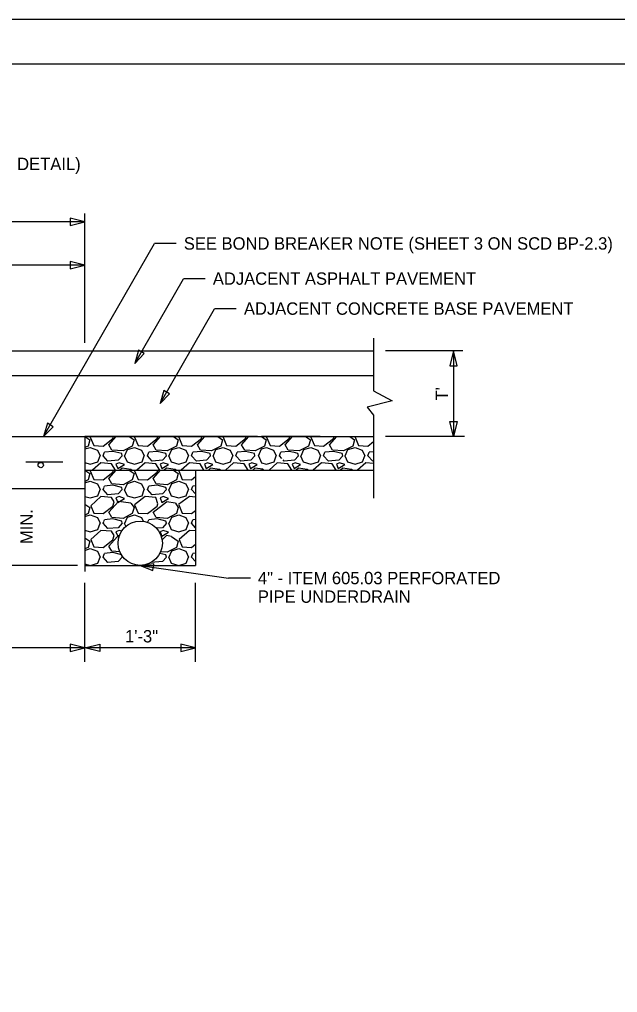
# Model space of a CAD drawing. Extents: x -529 to 1, y -1131 to -115.
# Drawn here: x -332.7 to -265.2, y -1020.8 to -910.8 of the extents above; entities that cross this region are included whole.
import ezdxf

# ---------------------------------------------------------------- set-up
doc = ezdxf.new("R2010")
doc.units = 0
for name, color, linetype in [('SH_Border', 7, 'Continuous'), ('SH_Cut_Line', 7, 'Continuous'), ('SH_Data', 7, 'Continuous'), ('SH_Text', 7, 'Continuous'), ('TX_X_5', 7, 'Continuous')]:
    doc.layers.add(name, color=color, linetype=linetype)

msp = doc.modelspace()

# ---------------------------------------------------------------- linework, layer by layer
at = {"layer": 'SH_Border'}
msp.add_lwpolyline([(-509.28, -915.76), (-194.28, -915.76), (-194.28, -1125.76), (-509.28, -1125.76)], close=True, dxfattribs=at)
at = {"layer": 'SH_Cut_Line'}
msp.add_lwpolyline([(-529.28, -1130.76), (-189.28, -1130.76), (-189.28, -910.76), (-529.28, -910.76)], close=True, dxfattribs=at)
at = {"layer": 'SH_Data'}
for p, q in [((-414.82, -948.22), (-292.72, -948.22)), ((-345.34, -951), (-292.72, -951)), ((-365.34, -957.9), (-292.72, -957.9)), ((-325.34, -957.9), (-325.34, -972.47)), ((-325.34, -957.9), (-305.86, -957.9)), ((-318.7, -957.9), (-325.34, -957.9)), ((-325.34, -957.9), (-325.34, -961.11)), ((-325.34, -957.9), (-324.79, -958.28)), ((-324.74, -957.9), (-324.74, -957.98)), ((-324.74, -957.98), (-324.34, -958.93)), ((-322.64, -958.83), (-321.81, -957.9)), ((-322.19, -958.13), (-322.12, -957.9)), ((-320.34, -957.9), (-319.79, -958.28)), ((-319.74, -957.9), (-319.74, -957.98)), ((-319.74, -957.98), (-319.34, -958.93)), ((-305.86, -957.9), (-318.7, -957.9)), ((-317.64, -958.83), (-316.81, -957.9)), ((-317.19, -958.13), (-317.12, -957.9)), ((-315.34, -957.9), (-314.79, -958.28)), ((-314.74, -957.9), (-314.74, -957.98)), ((-314.74, -957.98), (-314.34, -958.93)), ((-312.64, -958.83), (-311.81, -957.9)), ((-312.19, -958.13), (-312.12, -957.9)), ((-310.34, -957.9), (-309.79, -958.28)), ((-309.74, -957.9), (-309.74, -957.98)), ((-309.74, -957.98), (-309.34, -958.93)), ((-307.64, -958.83), (-306.81, -957.9)), ((-307.19, -958.13), (-307.12, -957.9)), ((-298.77, -957.9), (-305.41, -957.9)), ((-305.41, -957.9), (-304.87, -958.28)), ((-304.81, -957.9), (-304.82, -957.98)), ((-304.82, -957.98), (-304.42, -958.93)), ((-302.72, -958.83), (-301.88, -957.9)), ((-302.27, -958.13), (-302.19, -957.9)), ((-300.41, -957.9), (-299.87, -958.28)), ((-299.81, -957.9), (-299.82, -957.98)), ((-299.82, -957.98), (-299.42, -958.93)), ((-297.72, -958.83), (-296.88, -957.9)), ((-297.27, -958.13), (-297.19, -957.9)), ((-295.41, -957.9), (-294.87, -958.28)), ((-294.81, -957.9), (-294.82, -957.98)), ((-294.82, -957.98), (-294.42, -958.93)), ((-324.99, -958.98), (-325.34, -959.16)), ((-325.34, -959.31), (-324.74, -959.13)), ((-324.79, -958.28), (-324.99, -958.98)), ((-324.74, -959.13), (-323.94, -959.43)), ((-324.34, -958.93), (-323.29, -958.98)), ((-323.29, -958.98), (-322.19, -958.13)), ((-322.29, -959.43), (-322.64, -958.83)), ((-319.99, -958.98), (-321.04, -959.53)), ((-320.54, -959.38), (-319.74, -959.13)), ((-319.79, -958.28), (-319.99, -958.98)), ((-319.74, -959.13), (-318.94, -959.43)), ((-319.34, -958.93), (-318.29, -958.98)), ((-318.29, -958.98), (-317.19, -958.13)), ((-317.29, -959.43), (-317.64, -958.83)), ((-314.99, -958.98), (-316.04, -959.53)), ((-315.54, -959.38), (-314.74, -959.13)), ((-314.79, -958.28), (-314.99, -958.98)), ((-314.74, -959.13), (-313.94, -959.43)), ((-314.34, -958.93), (-313.29, -958.98)), ((-313.29, -958.98), (-312.19, -958.13)), ((-312.29, -959.43), (-312.64, -958.83)), ((-309.99, -958.98), (-311.04, -959.53)), ((-310.54, -959.38), (-309.74, -959.13)), ((-309.79, -958.28), (-309.99, -958.98)), ((-309.74, -959.13), (-308.94, -959.43)), ((-309.34, -958.93), (-308.29, -958.98)), ((-308.29, -958.98), (-307.19, -958.13)), ((-307.29, -959.43), (-307.64, -958.83)), ((-305.07, -958.99), (-306.1, -959.52)), ((-305.4, -959.31), (-304.82, -959.13)), ((-304.87, -958.28), (-305.07, -958.99)), ((-304.82, -959.13), (-304.02, -959.43)), ((-304.42, -958.93), (-303.37, -958.98)), ((-303.37, -958.98), (-302.27, -958.13)), ((-302.37, -959.43), (-302.72, -958.83)), ((-300.07, -958.98), (-301.12, -959.53)), ((-300.62, -959.38), (-299.82, -959.13)), ((-299.87, -958.28), (-300.07, -958.98)), ((-299.82, -959.13), (-299.02, -959.43)), ((-299.42, -958.93), (-298.37, -958.98)), ((-298.37, -958.98), (-297.27, -958.13)), ((-297.37, -959.43), (-297.72, -958.83)), ((-295.07, -958.98), (-296.12, -959.53)), ((-295.62, -959.38), (-294.82, -959.13)), ((-294.87, -958.28), (-295.07, -958.98)), ((-294.82, -959.13), (-294.02, -959.43)), ((-294.42, -958.93), (-293.37, -958.98)), ((-293.37, -958.98), (-292.72, -958.48)), ((-323.94, -959.43), (-323.64, -960.08)), ((-323.89, -960.78), (-323.64, -960.08)), ((-323.29, -960.08), (-323.22, -959.87)), ((-322.74, -960.68), (-323.29, -960.08)), ((-323.21, -959.86), (-323.14, -959.68)), ((-322.19, -959.58), (-323.14, -959.68)), ((-321.04, -959.53), (-322.29, -959.43)), ((-321.19, -959.83), (-322.19, -959.58)), ((-321.14, -960.08), (-321.59, -960.58)), ((-321.14, -960.08), (-321.19, -959.83)), ((-320.87, -960.14), (-320.54, -959.38)), ((-320.87, -960.14), (-320.59, -960.78)), ((-318.94, -959.43), (-318.64, -960.08)), ((-318.89, -960.78), (-318.64, -960.08)), ((-318.29, -960.08), (-318.14, -959.68)), ((-317.74, -960.68), (-318.29, -960.08)), ((-317.19, -959.58), (-318.14, -959.68)), ((-316.04, -959.53), (-317.29, -959.43)), ((-316.19, -959.83), (-317.19, -959.58)), ((-316.14, -960.08), (-316.59, -960.58)), ((-316.14, -960.08), (-316.19, -959.83)), ((-315.87, -960.14), (-315.54, -959.38)), ((-315.87, -960.14), (-315.59, -960.78)), ((-313.94, -959.43), (-313.64, -960.08)), ((-313.89, -960.78), (-313.64, -960.08)), ((-313.29, -960.08), (-313.14, -959.68)), ((-312.74, -960.68), (-313.29, -960.08)), ((-312.19, -959.58), (-313.14, -959.68)), ((-311.04, -959.53), (-312.29, -959.43)), ((-311.19, -959.83), (-312.19, -959.58)), ((-311.14, -960.08), (-311.59, -960.58)), ((-311.14, -960.08), (-311.19, -959.83)), ((-310.87, -960.14), (-310.54, -959.38)), ((-310.87, -960.14), (-310.59, -960.78)), ((-308.94, -959.43), (-308.64, -960.08)), ((-308.89, -960.78), (-308.64, -960.08)), ((-308.29, -960.08), (-308.14, -959.68)), ((-307.74, -960.68), (-308.29, -960.08)), ((-307.19, -959.58), (-308.14, -959.68)), ((-306.1, -959.52), (-307.29, -959.43)), ((-306.19, -959.83), (-307.19, -959.58)), ((-306.14, -960.08), (-306.59, -960.58)), ((-306.14, -960.08), (-306.19, -959.83)), ((-305.73, -960.08), (-305.4, -959.31)), ((-305.73, -960.08), (-305.39, -960.86)), ((-304.02, -959.43), (-303.72, -960.08)), ((-303.97, -960.78), (-303.72, -960.08)), ((-303.37, -960.08), (-303.29, -959.87)), ((-303.08, -960.39), (-303.37, -960.08)), ((-303.28, -959.86), (-303.22, -959.68)), ((-302.27, -959.58), (-303.22, -959.68)), ((-301.12, -959.53), (-302.37, -959.43)), ((-301.9, -959.67), (-302.27, -959.58)), ((-301.27, -959.83), (-301.81, -959.69)), ((-301.22, -960.08), (-301.67, -960.58)), ((-301.22, -960.08), (-301.27, -959.83)), ((-300.97, -960.08), (-300.67, -960.78)), ((-300.92, -960.08), (-300.62, -959.38)), ((-299.02, -959.43), (-298.72, -960.08)), ((-298.97, -960.78), (-298.72, -960.08)), ((-298.37, -960.08), (-298.22, -959.68)), ((-297.82, -960.68), (-298.37, -960.08)), ((-297.27, -959.58), (-298.22, -959.68)), ((-296.12, -959.53), (-297.37, -959.43)), ((-296.27, -959.83), (-297.27, -959.58)), ((-296.22, -960.08), (-296.67, -960.58)), ((-296.22, -960.08), (-296.27, -959.83)), ((-295.97, -960.08), (-295.67, -960.78)), ((-295.92, -960.08), (-295.62, -959.38)), ((-294.02, -959.43), (-293.72, -960.08)), ((-293.97, -960.78), (-293.72, -960.08)), ((-293.37, -960.08), (-293.22, -959.68)), ((-292.82, -960.68), (-293.37, -960.08)), ((-292.72, -959.63), (-293.22, -959.68)), ((-332.04, -960.76), (-327.84, -960.76)), ((-325.34, -960.85), (-324.74, -961.03)), ((-325.34, -961.11), (-325.34, -961.72)), ((-324.74, -961.03), (-323.89, -960.78)), ((-323.54, -960.88), (-324.47, -961.72)), ((-322.34, -960.98), (-323.54, -960.88)), ((-321.59, -960.58), (-322.74, -960.68)), ((-321.89, -961.72), (-322.34, -960.98)), ((-321.49, -960.88), (-321.84, -961.03)), ((-321.84, -961.03), (-321.64, -961.53)), ((-321.64, -961.53), (-320.89, -961.08)), ((-320.89, -961.08), (-321.49, -960.88)), ((-320.59, -960.78), (-319.74, -961.03)), ((-319.74, -961.03), (-318.89, -960.78)), ((-318.54, -960.88), (-319.47, -961.72)), ((-317.34, -960.98), (-318.54, -960.88)), ((-316.59, -960.58), (-317.74, -960.68)), ((-316.89, -961.72), (-317.34, -960.98)), ((-316.49, -960.88), (-316.84, -961.03)), ((-316.84, -961.03), (-316.64, -961.53)), ((-316.64, -961.53), (-315.89, -961.08)), ((-315.89, -961.08), (-316.49, -960.88)), ((-315.59, -960.78), (-314.74, -961.03)), ((-314.74, -961.03), (-313.89, -960.78)), ((-313.54, -960.88), (-314.47, -961.72)), ((-312.34, -960.98), (-313.54, -960.88)), ((-311.59, -960.58), (-312.74, -960.68)), ((-311.89, -961.72), (-312.34, -960.98)), ((-311.49, -960.88), (-311.84, -961.03)), ((-311.84, -961.03), (-311.64, -961.53)), ((-311.64, -961.53), (-310.89, -961.08)), ((-310.89, -961.08), (-311.49, -960.88)), ((-310.59, -960.78), (-309.74, -961.03)), ((-309.74, -961.03), (-308.89, -960.78)), ((-308.54, -960.88), (-309.47, -961.72)), ((-307.34, -960.98), (-308.54, -960.88)), ((-306.59, -960.58), (-307.74, -960.68)), ((-306.89, -961.72), (-307.34, -960.98)), ((-306.49, -960.88), (-306.84, -961.03)), ((-306.84, -961.03), (-306.64, -961.53)), ((-306.64, -961.53), (-305.89, -961.08)), ((-305.89, -961.08), (-306.49, -960.88)), ((-305.39, -960.86), (-304.82, -961.03)), ((-304.82, -961.03), (-303.97, -960.78)), ((-303.62, -960.88), (-304.54, -961.72)), ((-302.42, -960.98), (-303.62, -960.88)), ((-302.82, -960.68), (-302.96, -960.52)), ((-301.67, -960.58), (-302.82, -960.68)), ((-301.96, -961.72), (-302.42, -960.98)), ((-301.57, -960.88), (-301.92, -961.03)), ((-301.92, -961.03), (-301.72, -961.53)), ((-301.72, -961.53), (-300.97, -961.08)), ((-300.97, -961.08), (-301.57, -960.88)), ((-300.67, -960.78), (-299.82, -961.03)), ((-299.82, -961.03), (-298.97, -960.78)), ((-298.62, -960.88), (-299.54, -961.72)), ((-297.42, -960.98), (-298.62, -960.88)), ((-296.67, -960.58), (-297.82, -960.68)), ((-296.96, -961.72), (-297.42, -960.98)), ((-296.57, -960.88), (-296.92, -961.03)), ((-296.92, -961.03), (-296.72, -961.53)), ((-296.72, -961.53), (-295.97, -961.08)), ((-295.97, -961.08), (-296.57, -960.88)), ((-295.67, -960.78), (-294.82, -961.03)), ((-294.82, -961.03), (-293.97, -960.78)), ((-293.62, -960.88), (-294.54, -961.72)), ((-292.72, -960.95), (-293.62, -960.88)), ((-292.72, -960.67), (-292.82, -960.68)), ((-325.34, -961.72), (-292.72, -961.72)), ((-325.34, -961.72), (-305.86, -961.72)), ((-325.34, -961.72), (-325.34, -964.93)), ((-325.34, -961.72), (-324.79, -962.1)), ((-324.79, -962.1), (-324.99, -962.8)), ((-324.74, -961.72), (-324.74, -961.8)), ((-324.74, -961.8), (-324.34, -962.75)), ((-323.29, -962.8), (-322.19, -961.95)), ((-322.64, -962.65), (-321.81, -961.72)), ((-322.19, -961.95), (-322.12, -961.72)), ((-321.14, -961.48), (-321.39, -961.72)), ((-320.14, -961.63), (-321.14, -961.48)), ((-320.34, -961.72), (-319.79, -962.1)), ((-320.04, -961.72), (-320.14, -961.63)), ((-319.79, -962.1), (-319.99, -962.8)), ((-319.74, -961.72), (-319.74, -961.8)), ((-319.74, -961.8), (-319.34, -962.75)), ((-318.29, -962.8), (-317.19, -961.95)), ((-317.64, -962.65), (-316.81, -961.72)), ((-317.19, -961.95), (-317.12, -961.72)), ((-316.14, -961.48), (-316.39, -961.72)), ((-315.14, -961.63), (-316.14, -961.48)), ((-315.34, -961.72), (-314.79, -962.1)), ((-315.04, -961.72), (-315.14, -961.63)), ((-314.79, -962.1), (-314.99, -962.8)), ((-314.74, -961.72), (-314.74, -961.8)), ((-314.74, -961.8), (-314.34, -962.75)), ((-313.29, -962.8), (-312.84, -962.44)), ((-312.84, -961.72), (-312.84, -972.47)), ((-311.14, -961.48), (-311.39, -961.72)), ((-310.14, -961.63), (-311.14, -961.48)), ((-310.04, -961.72), (-310.14, -961.63)), ((-306.14, -961.48), (-306.39, -961.72)), ((-305.23, -961.61), (-306.14, -961.48)), ((-305.22, -961.63), (-305.41, -961.6)), ((-305.11, -961.72), (-305.23, -961.61)), ((-301.22, -961.48), (-301.46, -961.72)), ((-300.22, -961.63), (-301.22, -961.48)), ((-300.11, -961.72), (-300.22, -961.63)), ((-296.22, -961.48), (-296.46, -961.72)), ((-295.22, -961.63), (-296.22, -961.48)), ((-295.11, -961.72), (-295.22, -961.63)), ((-324.99, -962.8), (-325.34, -962.98)), ((-325.34, -963.13), (-324.74, -962.95)), ((-324.74, -962.95), (-323.94, -963.25)), ((-324.34, -962.75), (-323.29, -962.8)), ((-323.94, -963.25), (-323.64, -963.9)), ((-323.21, -963.68), (-323.14, -963.5)), ((-322.19, -963.4), (-323.14, -963.5)), ((-322.29, -963.25), (-322.64, -962.65)), ((-321.04, -963.35), (-322.29, -963.25)), ((-321.19, -963.65), (-322.19, -963.4)), ((-319.99, -962.8), (-321.04, -963.35)), ((-320.87, -963.95), (-320.54, -963.2)), ((-320.54, -963.2), (-319.74, -962.95)), ((-319.74, -962.95), (-318.94, -963.25)), ((-319.34, -962.75), (-318.29, -962.8)), ((-318.94, -963.25), (-318.64, -963.9)), ((-318.29, -963.9), (-318.14, -963.5)), ((-317.19, -963.4), (-318.14, -963.5)), ((-317.29, -963.25), (-317.64, -962.65)), ((-316.04, -963.35), (-317.29, -963.25)), ((-316.19, -963.65), (-317.19, -963.4)), ((-314.99, -962.8), (-316.04, -963.35)), ((-315.87, -963.95), (-315.54, -963.2)), ((-315.54, -963.2), (-314.74, -962.95)), ((-314.74, -962.95), (-313.94, -963.25)), ((-314.34, -962.75), (-313.29, -962.8)), ((-313.94, -963.25), (-313.64, -963.9)), ((-313.29, -963.9), (-313.14, -963.5)), ((-312.84, -963.46), (-313.14, -963.5)), ((-395.34, -963.77), (-325.34, -963.77)), ((-325.34, -964.67), (-324.74, -964.85)), ((-324.74, -964.85), (-323.89, -964.6)), ((-323.54, -964.7), (-324.69, -965.74)), ((-323.89, -964.6), (-323.64, -963.9)), ((-322.34, -964.8), (-323.54, -964.7)), ((-323.29, -963.9), (-323.22, -963.69)), ((-322.74, -964.5), (-323.28, -963.91)), ((-321.59, -964.4), (-322.74, -964.5)), ((-321.49, -964.7), (-321.84, -964.85)), ((-321.14, -963.9), (-321.59, -964.4)), ((-320.89, -964.9), (-321.49, -964.7)), ((-321.14, -963.9), (-321.19, -963.65)), ((-320.87, -963.95), (-320.59, -964.6)), ((-320.59, -964.6), (-319.74, -964.85)), ((-318.54, -964.7), (-319.76, -965.62)), ((-319.74, -964.85), (-318.89, -964.6)), ((-318.89, -964.6), (-318.64, -963.9)), ((-317.34, -964.8), (-318.54, -964.7)), ((-317.74, -964.5), (-318.29, -963.9)), ((-316.59, -964.4), (-317.74, -964.5)), ((-316.49, -964.7), (-316.84, -964.85)), ((-316.14, -963.9), (-316.59, -964.4)), ((-315.89, -964.9), (-316.49, -964.7)), ((-316.14, -963.9), (-316.19, -963.65)), ((-315.87, -963.95), (-315.59, -964.6)), ((-315.59, -964.6), (-314.74, -964.85)), ((-313.54, -964.7), (-314.77, -965.59)), ((-314.74, -964.85), (-313.89, -964.6)), ((-313.89, -964.6), (-313.64, -963.9)), ((-312.84, -964.75), (-313.54, -964.7)), ((-312.84, -964.39), (-313.29, -963.9)), ((-325.34, -964.93), (-325.34, -965.54)), ((-325.34, -965.54), (-325.34, -968.75)), ((-325.34, -965.54), (-324.79, -965.91)), ((-324.69, -965.74), (-324.34, -966.56)), ((-323.29, -966.61), (-322.19, -965.76)), ((-322.64, -966.46), (-321.54, -965.24)), ((-322.04, -965.29), (-322.34, -964.8)), ((-322.19, -965.76), (-322.04, -965.29)), ((-321.84, -964.85), (-321.64, -965.35)), ((-321.64, -965.35), (-320.89, -964.9)), ((-320.14, -965.45), (-321.54, -965.24)), ((-320.17, -965.45), (-319.79, -965.91)), ((-319.74, -965.61), (-319.34, -966.56)), ((-318.29, -966.61), (-317.19, -965.76)), ((-317.64, -966.46), (-316.14, -965.28)), ((-317.12, -965.53), (-317.34, -964.8)), ((-317.19, -965.76), (-317.12, -965.53)), ((-316.84, -964.85), (-316.64, -965.35)), ((-316.64, -965.35), (-315.89, -964.9)), ((-315.11, -965.45), (-316.14, -965.3)), ((-315.11, -965.45), (-314.79, -965.91)), ((-314.74, -965.61), (-314.34, -966.56)), ((-324.99, -966.61), (-325.34, -966.79)), ((-325.34, -966.95), (-324.74, -966.76)), ((-324.79, -965.91), (-324.99, -966.61)), ((-324.74, -966.76), (-323.94, -967.06)), ((-324.34, -966.56), (-323.29, -966.61)), ((-322.29, -967.06), (-322.64, -966.46)), ((-319.99, -966.61), (-321.04, -967.16)), ((-320.54, -967.01), (-319.74, -966.76)), ((-319.79, -965.91), (-319.99, -966.61)), ((-319.74, -966.76), (-318.94, -967.06)), ((-319.34, -966.56), (-318.29, -966.61)), ((-317.29, -967.06), (-317.64, -966.46)), ((-314.99, -966.61), (-316.04, -967.16)), ((-315.54, -967.01), (-314.74, -966.76)), ((-314.79, -965.91), (-314.99, -966.61)), ((-314.74, -966.76), (-313.94, -967.06)), ((-314.34, -966.56), (-313.29, -966.61)), ((-313.29, -966.61), (-312.84, -966.26)), ((-323.94, -967.06), (-323.64, -967.71)), ((-323.89, -968.41), (-323.64, -967.71)), ((-323.29, -967.71), (-323.22, -967.5)), ((-322.74, -968.31), (-323.29, -967.71)), ((-323.21, -967.49), (-323.14, -967.31)), ((-322.19, -967.21), (-323.14, -967.31)), ((-321.04, -967.16), (-322.29, -967.06)), ((-321.19, -967.46), (-322.19, -967.21)), ((-321.14, -967.71), (-321.59, -968.21)), ((-321.14, -967.71), (-321.19, -967.46)), ((-320.87, -967.77), (-320.54, -967.01)), ((-320.87, -967.77), (-320.73, -968.08)), ((-318.94, -967.06), (-318.75, -967.49)), ((-318.26, -967.61), (-318.14, -967.31)), ((-317.19, -967.21), (-318.14, -967.31)), ((-316.04, -967.16), (-317.29, -967.06)), ((-316.19, -967.46), (-317.19, -967.21)), ((-316.14, -967.71), (-316.59, -968.21)), ((-316.14, -967.71), (-316.19, -967.46)), ((-315.87, -967.77), (-315.54, -967.01)), ((-315.87, -967.77), (-315.59, -968.41)), ((-313.94, -967.06), (-313.64, -967.71)), ((-313.89, -968.41), (-313.64, -967.71)), ((-313.29, -967.71), (-313.14, -967.31)), ((-312.84, -968.21), (-313.29, -967.71)), ((-312.84, -967.28), (-313.14, -967.31)), ((-325.34, -968.49), (-324.74, -968.66)), ((-325.34, -968.75), (-325.34, -969.36)), ((-324.74, -968.66), (-323.89, -968.41)), ((-323.54, -968.51), (-324.69, -969.56)), ((-322.34, -968.61), (-323.54, -968.51)), ((-321.59, -968.21), (-322.74, -968.31)), ((-322.04, -969.11), (-322.34, -968.61)), ((-321.49, -968.51), (-321.84, -968.66)), ((-321.84, -968.66), (-321.64, -969.16)), ((-321.64, -969.16), (-321.4, -969.02)), ((-321.19, -968.61), (-321.49, -968.51)), ((-316.59, -968.21), (-317.25, -968.27)), ((-316.49, -968.51), (-316.84, -968.66)), ((-316.84, -968.66), (-316.64, -969.16)), ((-316.64, -969.16), (-315.89, -968.71)), ((-315.89, -968.71), (-316.49, -968.51)), ((-315.59, -968.41), (-314.74, -968.66)), ((-314.74, -968.66), (-313.89, -968.41)), ((-313.54, -968.51), (-314.69, -969.56)), ((-312.84, -968.57), (-313.54, -968.51)), ((-325.34, -969.36), (-325.34, -972.57)), ((-325.34, -969.36), (-324.79, -969.73)), ((-324.79, -969.73), (-324.99, -970.43)), ((-324.69, -969.56), (-324.34, -970.38)), ((-323.29, -970.43), (-322.19, -969.58)), ((-322.64, -970.28), (-321.72, -969.25)), ((-322.19, -969.58), (-322.04, -969.11)), ((-321.49, -969.27), (-321.72, -969.25)), ((-316.14, -969.11), (-316.62, -969.59)), ((-315.56, -969.2), (-316.14, -969.11)), ((-315.56, -969.2), (-314.79, -969.73)), ((-314.79, -969.73), (-314.99, -970.43)), ((-314.69, -969.56), (-314.34, -970.38)), ((-313.29, -970.43), (-312.84, -970.08)), ((-324.99, -970.43), (-325.34, -970.61)), ((-325.34, -970.77), (-324.74, -970.58)), ((-324.74, -970.58), (-323.94, -970.88)), ((-324.34, -970.38), (-323.29, -970.43)), ((-323.94, -970.88), (-323.64, -971.53)), ((-323.21, -971.31), (-323.14, -971.13)), ((-322.19, -971.03), (-323.14, -971.13)), ((-322.29, -970.88), (-322.64, -970.28)), ((-321.39, -970.95), (-322.29, -970.88)), ((-321.19, -971.28), (-322.19, -971.03)), ((-321.14, -971.53), (-321.19, -971.28)), ((-316.19, -971.28), (-316.87, -971.11)), ((-316.04, -970.98), (-316.78, -970.92)), ((-316.14, -971.53), (-316.19, -971.28)), ((-314.99, -970.43), (-316.04, -970.98)), ((-315.87, -971.59), (-315.54, -970.83)), ((-315.54, -970.83), (-314.74, -970.58)), ((-314.74, -970.58), (-313.94, -970.88)), ((-314.34, -970.38), (-313.29, -970.43)), ((-313.94, -970.88), (-313.64, -971.53)), ((-313.29, -971.53), (-313.14, -971.13)), ((-312.84, -971.1), (-313.14, -971.13)), ((-325.34, -972.31), (-324.74, -972.48)), ((-324.74, -972.48), (-323.89, -972.23)), ((-323.89, -972.23), (-323.64, -971.53)), ((-323.29, -971.53), (-323.22, -971.32)), ((-322.74, -972.13), (-323.29, -971.53)), ((-321.59, -972.03), (-322.74, -972.13)), ((-321.14, -971.53), (-321.59, -972.03)), ((-316.59, -972.03), (-317.86, -972.14)), ((-316.14, -971.53), (-316.59, -972.03)), ((-315.87, -971.59), (-315.59, -972.23)), ((-315.59, -972.23), (-314.74, -972.48)), ((-314.74, -972.48), (-313.89, -972.23)), ((-313.89, -972.23), (-313.64, -971.53)), ((-312.84, -972.03), (-313.29, -971.53)), ((-325.34, -972.47), (-312.84, -972.47)), ((-325.34, -972.57), (-325.34, -973.17))]:
    msp.add_line(p, q, dxfattribs=at)
for points in [[(-292.72, -946.78), (-292.72, -952.75), (-290.62, -953.87), (-293.44, -954.59), (-292.72, -955.48), (-292.72, -964.88)], [(-325.34, -961.72), (-318.7, -961.72), (-305.86, -961.72)]]:
    msp.add_lwpolyline(points, dxfattribs=at)
for centre, radius in [((-330.34, -961.13), 0.3), ((-319.09, -969.97), 2.5)]:
    msp.add_circle(centre, radius, dxfattribs=at)
at = {"layer": 'SH_Text'}
for p, q in [((-325.34, -947.31), (-325.34, -932.7)), ((-325.34, -933.63), (-395.34, -933.63)), ((-325.34, -938.54), (-395.34, -938.54)), ((-282.63, -948.22), (-291.39, -948.22)), ((-283.69, -948.22), (-283.69, -957.9)), ((-282.44, -957.9), (-291.39, -957.9)), ((-326.18, -972.47), (-334.28, -972.47)), ((-325.34, -983.37), (-325.34, -974.43)), ((-312.84, -983.37), (-312.84, -974.43)), ((-312.84, -981.78), (-395.34, -981.78))]:
    msp.add_line(p, q, dxfattribs=at)
for points in [[(-327.02, -934.05), (-325.34, -933.63), (-327.02, -933.21)], [(-327.02, -938.96), (-325.34, -938.54), (-327.02, -938.12)], [(-283.27, -949.9), (-283.69, -948.22), (-284.11, -949.9)], [(-283.27, -956.22), (-283.69, -957.9), (-284.11, -956.22)], [(-327.02, -982.2), (-325.34, -981.78), (-327.02, -981.36)], [(-323.66, -982.2), (-325.34, -981.78), (-323.66, -981.36)], [(-314.52, -982.2), (-312.84, -981.78), (-314.52, -981.36)]]:
    msp.add_lwpolyline(points, close=True, dxfattribs=at)
at = {"layer": 'TX_X_5'}
for p, q in [((-330.01, -957.9), (-317.5, -936.1)), ((-315.03, -936.1), (-317.5, -936.1)), ((-319.71, -949.64), (-314.22, -940.07)), ((-311.74, -940.07), (-314.22, -940.07)), ((-316.86, -954.18), (-310.71, -943.46)), ((-308.24, -943.46), (-310.71, -943.46)), ((-319.09, -972.47), (-309.12, -973.93)), ((-306.65, -973.93), (-309.12, -973.93))]:
    msp.add_line(p, q, dxfattribs=at)
for points in [[(-319.29, -948.15), (-319.71, -949.64), (-318.64, -948.52)], [(-316.44, -952.69), (-316.86, -954.18), (-315.79, -953.06)], [(-329.59, -956.41), (-330.01, -957.9), (-328.94, -956.79)], [(-317.55, -972.31), (-319.09, -972.47), (-317.66, -973.06)]]:
    msp.add_lwpolyline(points, close=True, dxfattribs=at)

# ---------------------------------------------------------------- texts
at = {"layer": 'SH_Data'}
for s, p in [('CONCRETE BAND (SEE TYPICAL CONCRETE BAND DETAIL)', (-379.71, -927.79)), ('SEE BOND BREAKER NOTE (SHEET 3 ON SCD BP-2.3)', (-314.17, -936.78)), ('ADJACENT ASPHALT PAVEMENT', (-310.89, -940.75)), ('ADJACENT CONCRETE BASE PAVEMENT', (-307.38, -944.14)), ('4" - ITEM 605.03 PERFORATED', (-305.8, -974.6)), ('PIPE UNDERDRAIN', (-305.8, -976.7))]:
    msp.add_text(s, height=1.4, dxfattribs=at).set_placement(p)
at = {"layer": 'SH_Text'}
for s, rotation, p in [("T'", 90, (-284.31, -953.83)), ('MIN.', 90, (-331.24, -970.06)), ('1\'-3"', 360, (-320.81, -981.18))]:
    msp.add_text(s, height=1.4, rotation=rotation, dxfattribs=at).set_placement(p)

doc.saveas('drawing.dxf')
